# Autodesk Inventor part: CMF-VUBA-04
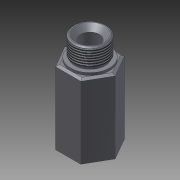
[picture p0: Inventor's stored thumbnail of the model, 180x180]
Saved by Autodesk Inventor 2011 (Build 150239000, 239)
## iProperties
Created: 2016-10
Part Number: CMF-VUBA-04
Material: Сталь
Document SubType Name: Modeling
Designer: Хитров
Density: 7.85 g/cm^3
Author: Хитров
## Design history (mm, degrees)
sketch "Эскиз1"
  geometry: L1 (20.207, 0)-(10.104, -17.5); L2 (10.104, -17.5)-(-10.104, -17.5); L3 (-10.104, -17.5)-(-20.207, 0); L4 (-20.207, 0)-(-10.104, 17.5); L5 (-10.104, 17.5)-(10.104, 17.5); L6 (10.104, 17.5)-(20.207, 0); 2 further points
  constraints: 12 end point, 1 coincident, 1 horizontal alignment, 13 other
  dimensions: "d0" = 35 distance between parallel lines of L2 L5
extrude "Выдавливание1" new body sketch "Эскиз1" distance "d1" = 60; taper "d2" = 0 deg
chamfer "Фаска1" distance "d3" = 2; stored, may be unused: second distance "d4" = 2, angle "d5" = 30 deg
chamfer "Фаска2" distance "d6" = 2; stored, may be unused: second distance "d7" = 2, angle "d8" = 30 deg
sketch "Эскиз2"
  geometry: C1 r 15.5 at (0, 0); 1 further point
  constraints: 1 centre point, 1 coincident
extrude "Выдавливание2" join sketch "Эскиз2" distance "d9" = 2; taper "d10" = 0 deg
sketch "Эскиз3"
  geometry: C1 r 15.5 at (0, 0) reference; C2 r 13.22 at (0, 0)
  constraints: 1 centre point, 1 coincident
  dimensions: "d11" = 26.441 diameter of C2
extrude "Выдавливание3" join sketch "Эскиз3" distance "d12" = 16; taper "d13" = 0 deg
sketch "Эскиз4"
  geometry: L1 (13.22, 62)-(13.22, 78) reference; L2 (-15.5, 62)-(15.5, 62) reference; L3 (13.22, 62)-(12.22, 62); L4 (12.22, 62)-(12.22, 63); L5 (12.22, 63)-(13.22, 63); L6 (13.22, 63)-(13.22, 62); L7 (0, -15.6)-(0, 93.6) reference; 1 further point
  constraints: 8 end point, 2 parallel, 1 horizontal, 1 perpendicular
  dimensions: "d14" = 1 distance of L5.end L1.start; "d15" = 1 distance of L4.end L5.end
revolve "Вращение1" sketch "Эскиз4" stored, may be unused: angle "d16" = 90 deg
feature "Резьба1" dims "d17" = 10, "d18" = 0
hole "Отверстие1" diameter "d24" = 24.117; stored, may be unused: countersink angle "d28" = 90 deg, drill point angle "d30" = 118 deg; dims "d22" = 10, "d23" = 10, "d25" = 45, "d26" = 4, "d27" = 2, "d29" = 55
chamfer "Фаска3" distance "d19" = 1; stored, may be unused: second distance "d20" = 2, angle "d21" = 30 deg
hole "Отверстие2" diameter "d33" = 15; stored, may be unused: countersink angle "d37" = 90 deg, drill point angle "d39" = 118 deg; dims "d31" = 10, "d32" = 10, "d34" = 45, "d35" = 4, "d36" = 2, "d38" = 55
chamfer "Фаска4" distance "d40" = 4; stored, may be unused: second distance "d41" = 2, angle "d42" = 30 deg
node "Твердое тело1"
